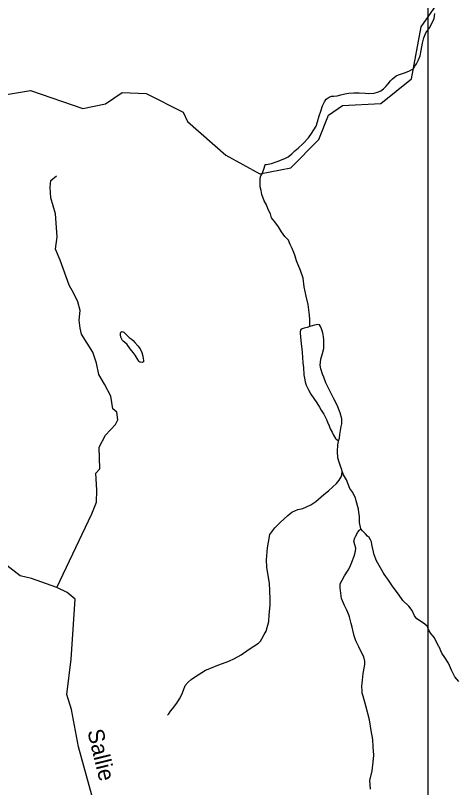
# Model space of a CAD drawing. Extents: x 2126262 to 2293712, y 749403 to 919119.
# Drawn here: x 2187256 to 2189866, y 811845 to 816398 of the extents above; entities that cross this region are included whole.
import ezdxf

# ---------------------------------------------------------------- set-up
doc = ezdxf.new("R2010")
doc.units = 0
for name, color, linetype in [('Exist Hydrographic Creek Single Shore', 7, 'Continuous'), ('Exist Hydrographic Misc Water Feature', 7, 'Continuous'), ('Exist Road Non-System Type 51', 7, 'Continuous'), ('Exist Road Non-System Type 51 Label', 7, 'Continuous'), ('Map Preparation Inset Cut Line', 7, 'Continuous')]:
    doc.layers.add(name, color=color, linetype=linetype)

msp = doc.modelspace()

# ---------------------------------------------------------------- linework, layer by layer
at = {"layer": 'Exist Hydrographic Creek Single Shore'}
msp.add_lwpolyline([(2187129.7, 815919.9), (2187345.6, 815954.8), (2187654.6, 815850.1), (2187787.7, 815876.8), (2187886.8, 815943.7), (2188028.7, 815937.4), (2188246.6, 815828), (2188271.6, 815771.7), (2188497.6, 815573.5), (2188698.8, 815464.4), (2188881.7, 815499.9), (2189046.7, 815667.1), (2189104.8, 815810.3), (2189187.6, 815867.6), (2189412.8, 815879.4), (2189594.6, 816023.2), (2189650.6, 816330.5), (2189782.7, 816521.3)], dxfattribs=at)
at = {"layer": 'Exist Hydrographic Misc Water Feature'}
for points in [[(2188730, 815519.8), (2188738, 815519.8), (2188768, 815524), (2188802, 815536.3), (2188845.9, 815554.6), (2188865.8, 815564.7), (2188887.5, 815582.8), (2188905.6, 815599), (2188925.7, 815615.1), (2188955.4, 815643.3), (2188985.1, 815675.5), (2189002.8, 815701.6), (2189018.5, 815723.7), (2189030.6, 815745.8), (2189038.2, 815769.8), (2189048.1, 815805.9), (2189057.9, 815834), (2189067.8, 815864), (2189079.7, 815888.1), (2189091.3, 815904.1), (2189107.3, 815916.3), (2189121.3, 815922.3), (2189127.2, 815922.4), (2189135.4, 815922.4), (2189155.3, 815924.6), (2189177.3, 815930.7), (2189201, 815934.9), (2189225, 815939.1), (2189253.1, 815941.3), (2189285.1, 815941.5), (2189321, 815939.7), (2189343.1, 815937.8), (2189373.1, 815940.1), (2189399.1, 815948.3), (2189413.1, 815954.3), (2189428.9, 815964.5), (2189442.8, 815978.5), (2189456.5, 815994.7), (2189470.5, 816012.7), (2189482.6, 816024.8), (2189504.3, 816041), (2189516.4, 816047), (2189534.3, 816053.2), (2189552.3, 816059.3), (2189568.1, 816065.4), (2189582, 816071.5), (2189596.2, 816079.6), (2189606, 816083.7), (2189613.8, 816099.7), (2189623.9, 816111.7), (2189635.5, 816135.8), (2189645.6, 816159.9), (2189651.3, 816191.9), (2189659.1, 816234), (2189666.9, 816266), (2189678.6, 816296), (2189702.4, 816326.2), (2189728, 816380.3), (2189731.9, 816410.4)], [(2188994.6, 814563.9), (2188994.4, 814605.8), (2188992.3, 814629.9), (2188983.9, 814693.8), (2188973.2, 814741.7), (2188961.1, 814797.6), (2188954.8, 814849.5), (2188938.4, 814893.4), (2188916, 814951.3), (2188907.8, 814979.2), (2188899.8, 814999.1), (2188889.6, 815023), (2188877.3, 815046.9), (2188867.2, 815072.9), (2188847.1, 815094.7), (2188826.8, 815122.6), (2188808.6, 815150.4), (2188786.6, 815180.3), (2188768.4, 815204.1), (2188762, 815228.1), (2188748.1, 815254), (2188737.8, 815281.9), (2188723.5, 815303.8), (2188711.4, 815341.7), (2188707.3, 815365.7), (2188701.1, 815387.6), (2188700.9, 815411.7), (2188700.9, 815437.6), (2188704.6, 815451.6), (2188712.6, 815463.7), (2188724.3, 815497.8), (2188728.4, 815511.8), (2188730, 815519.8)], [(2189163.3, 813889.2), (2189169.1, 813905.3), (2189171.1, 813927.3), (2189174.8, 813949.3), (2189178.5, 813973.3), (2189182.6, 813989.4), (2189182.4, 814019.3), (2189172.1, 814055.2), (2189155.7, 814099.1), (2189135.6, 814137), (2189111.2, 814184.8), (2189088.9, 814230.6), (2189076.6, 814264.5), (2189068.6, 814282.5), (2189058.3, 814314.4), (2189054, 814336.4), (2189058.1, 814370.3), (2189067.8, 814404.4), (2189075.6, 814434.5), (2189077.4, 814460.5), (2189077, 814484.5), (2189075.1, 814502.5), (2189070.8, 814526.4), (2189062.8, 814550.4), (2189056.5, 814564.3), (2189050.5, 814574.2), (2189046.6, 814574.2), (2189038.6, 814576.2), (2189030.6, 814574.1), (2189020.6, 814572.1), (2188994.6, 814563.9)], [(2187939.6, 814490.7), (2187951.7, 814480.7), (2187961.5, 814468.8), (2187977.9, 814448.9), (2187991.9, 814431), (2188002.1, 814411.1), (2188008.1, 814389.2), (2188010.3, 814375.2), (2188012.4, 814363.2), (2188012.4, 814355.2), (2188006.4, 814351.2), (2187994.3, 814353.1), (2187990.4, 814353.1), (2187984.3, 814359), (2187974.2, 814374.9), (2187962.1, 814394.9), (2187950, 814410.7), (2187933.8, 814432.6), (2187915.8, 814456.5), (2187899.6, 814470.4), (2187891.6, 814476.4), (2187887.5, 814480.3), (2187883.6, 814488.3), (2187877.2, 814500.2), (2187875.4, 814514.2), (2187875.4, 814526.2), (2187877.2, 814530.2), (2187883.4, 814534.2), (2187889.3, 814532.3), (2187895.3, 814530.3), (2187913.3, 814512.5), (2187927.3, 814498.6), (2187939.6, 814490.7)], [(2188994.6, 814563.9), (2188978.8, 814557.8), (2188960.7, 814553.7), (2188948.8, 814549.6), (2188942.9, 814547.6), (2188938.8, 814541.5), (2188936.7, 814533.5), (2188937.1, 814523.5), (2188941.2, 814481.5), (2188947.8, 814411.6), (2188952.1, 814349.7), (2188956.4, 814321.7), (2188958.5, 814277.7), (2188962.8, 814259.7), (2188966.9, 814237.8), (2188973, 814217.8), (2188985.3, 814189.9), (2188999.3, 814164.1), (2189017.5, 814138.2), (2189035.8, 814114.3), (2189051.8, 814088.4), (2189060, 814070.5), (2189076.2, 814046.6), (2189092.4, 814014.7), (2189098.5, 813998.8), (2189108.6, 813976.9), (2189114.7, 813960.9), (2189124.8, 813941), (2189133, 813923), (2189145.1, 813903.1), (2189149.2, 813899.2), (2189159.2, 813893.2), (2189163.3, 813889.2)], [(2189184.2, 813711.4), (2189182.4, 813717.4), (2189174.4, 813739.4), (2189168, 813763.3), (2189159.8, 813789.2), (2189157.6, 813827.2), (2189159.2, 813865.3), (2189163.3, 813885.2), (2189163.3, 813889.2)], [(2188154.5, 812270.8), (2188160.6, 812278.8), (2188170.5, 812294.9), (2188182.3, 812309), (2188208, 812343.2), (2188224, 812367.2), (2188237.7, 812393.3), (2188247.6, 812419.4), (2188257.4, 812445.5), (2188275.2, 812465.6), (2188293.1, 812481.7), (2188313, 812495.8), (2188335.1, 812510), (2188378.8, 812536.3), (2188412.6, 812550.5), (2188450.6, 812566.8), (2188478.6, 812577), (2188516.4, 812589.2), (2188548.4, 812605.4), (2188588.1, 812627.7), (2188635.7, 812660), (2188663.8, 812678.2), (2188691.5, 812696.4), (2188703.6, 812708.5), (2188711.4, 812722.5), (2188725.3, 812746.6), (2188737, 812766.6), (2188752.6, 812824.8), (2188754.2, 812862.8), (2188760, 812920.8), (2188759.8, 812956.8), (2188755.1, 813050.7), (2188748.9, 813094.7), (2188740.5, 813144.6), (2188738, 813188.5), (2188743.6, 813258.6), (2188749.5, 813292.6), (2188757.1, 813336.6), (2188786.8, 813376.8), (2188820.5, 813409.1), (2188840.6, 813427.2), (2188864.3, 813449.4), (2188888.3, 813469.5), (2188924, 813483.7), (2188952.1, 813489.9), (2188999.9, 813512.2), (2189029.8, 813532.4), (2189077.4, 813572.7), (2189103.2, 813594.9), (2189129.1, 813617.1), (2189151, 813637.2), (2189166.8, 813657.4), (2189178.5, 813677.4), (2189182.6, 813687.4), (2189184.2, 813711.4)], [(2189294.8, 813370.3), (2189286.5, 813408.2), (2189286.3, 813444.2), (2189284.1, 813466.2), (2189282, 813486.2), (2189267.5, 813536), (2189263.6, 813554), (2189255.4, 813566), (2189247.4, 813583.9), (2189231, 813607.8), (2189210.9, 813659.7), (2189192.6, 813689.5), (2189184.2, 813711.4)], [(2189351.3, 811835.1), (2189348.9, 811885.2), (2189362.6, 811943.2), (2189368, 811995.2), (2189371.9, 812035.3), (2189367.5, 812085.2), (2189365.3, 812127.1), (2189356.9, 812181.1), (2189346.6, 812243), (2189323.9, 812326.8), (2189309.5, 812382.7), (2189303.4, 812400.7), (2189303.4, 812416.7), (2189301.1, 812440.7), (2189303, 812460.6), (2189304.8, 812478.6), (2189308.5, 812516.7), (2189316.3, 812558.7), (2189318.3, 812572.7), (2189318.1, 812590.7), (2189311.8, 812614.6), (2189297.8, 812644.5), (2189283.5, 812674.5), (2189265.2, 812710.3), (2189255, 812740.2), (2189246.8, 812772.2), (2189242.9, 812790.2), (2189238.6, 812812.1), (2189228.3, 812852), (2189224.2, 812864), (2189212.1, 812889.9), (2189197.8, 812917.8), (2189181.6, 812959.6), (2189177.3, 812991.6), (2189173.2, 813021.6), (2189173.2, 813045.6), (2189184.8, 813067.7), (2189198.6, 813093.7), (2189220.5, 813125.8), (2189230.4, 813143.9), (2189242.1, 813174), (2189255.8, 813210.1), (2189263.6, 813238.2), (2189265.6, 813256.1), (2189259.3, 813276.1), (2189253.3, 813298), (2189259.1, 813318.1), (2189263, 813326.1), (2189273, 813342.2), (2189274.9, 813348.2), (2189286.8, 813362.2), (2189294.8, 813370.3)], [(2189872.8, 812470.5), (2189850.6, 812498.4), (2189830.3, 812536.2), (2189812.1, 812578.1), (2189791.8, 812612), (2189773.5, 812637.9), (2189757.3, 812673.7), (2189753.2, 812677.6), (2189729.1, 812727.5), (2189721.1, 812737.4), (2189708.8, 812753.4), (2189698.7, 812769.3), (2189692.6, 812783.2), (2189688.7, 812795.2), (2189672.5, 812809.1), (2189652.4, 812820.9), (2189626.3, 812838.7), (2189612, 812856.7), (2189598, 812888.5), (2189577.7, 812914.4), (2189543.5, 812948.2), (2189517.2, 812986), (2189485, 813025.7), (2189458.8, 813067.5), (2189432.5, 813103.3), (2189426.6, 813113.3), (2189388.1, 813181), (2189373.9, 813216.9), (2189359.3, 813278.8), (2189357.3, 813292.8), (2189353, 813304.7), (2189345, 813318.7), (2189335.1, 813326.6), (2189322.8, 813340.5), (2189304.8, 813358.4), (2189294.8, 813370.3)]]:
    msp.add_lwpolyline(points, dxfattribs=at)
at = {"layer": 'Exist Road Non-System Type 51'}
for points in [[(2187500.5, 813025.2), (2187706.4, 813458.3), (2187734.3, 813528.1), (2187737.1, 813598), (2187731.5, 813698.5), (2187753.8, 813723.7), (2187751, 813852.1), (2187787.7, 813923.2), (2187846.3, 813984.7), (2187860.2, 814014), (2187854.6, 814058.7), (2187830.9, 814078.2), (2187818.4, 814153.7), (2187782.1, 814224.2), (2187748.6, 814281.4), (2187734.7, 814347.1), (2187712.3, 814411.3), (2187646.8, 814517.4), (2187638.4, 814553.8), (2187632.8, 814601.2), (2187637.7, 814657.8), (2187625.1, 814709.5), (2187601.4, 814758.3), (2187573.5, 814807.2), (2187519.1, 814955.3), (2187491.9, 815020.2), (2187501.6, 815092.8), (2187491.9, 815228.3), (2187464, 815323.2), (2187461.2, 815386.1), (2187465.4, 815423.8), (2187497.5, 815451.7)], [(2187500.5, 813025.2), (2187351.2, 813076.8), (2187284.2, 813093.6), (2187206.1, 813155), (2187144.7, 813177.4), (2187086.1, 813163.4), (2187033.1, 813152.3), (2186823.8, 813129.9), (2186673.1, 813138.3), (2186625.6, 813152.3), (2186555.9, 813205.3), (2186514.4, 813236), (2186333, 813252.7), (2186219.1, 813216.5)], [(2188076.7, 810500), (2188084.3, 810647.2), (2188080.5, 810720.1), (2187960.7, 810935.2), (2187890.9, 811116.7), (2187849, 811246.9), (2187818.3, 811422.9), (2187759.7, 811598.8), (2187723.5, 811709.6), (2187706.7, 811798.9), (2187628.6, 812083.8), (2187587.1, 812305.8), (2187559.1, 812392.4), (2187584.3, 812601.9), (2187609.3, 812955.3), (2187561.9, 812994.5), (2187500.5, 813025.2)]]:
    msp.add_lwpolyline(points, dxfattribs=at)
at = {"layer": 'Map Preparation Inset Cut Line'}
msp.add_lwpolyline([(2133630.5, 852884.6), (2189691.2, 852884.6), (2189691.2, 811054.9), (2164878.1, 811054.9), (2133665.4, 826054.8)], close=True, dxfattribs=at)

# ---------------------------------------------------------------- texts
at = {"layer": 'Exist Road Non-System Type 51 Label'}
msp.add_text('Sallie', height=95, rotation=283.7954, dxfattribs=at).set_placement((2187679.6, 812177.3))

doc.saveas('drawing.dxf')
